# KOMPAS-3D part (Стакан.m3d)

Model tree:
1. Эскиз:1
2. Операция выдавливания:1
     Расстояние 1 = 70; Угол 1 = 4
3. Эскиз:2
4. Вырезать элемент выдавливания:1
     Расстояние 1 = 65; Угол 1 = 4
5. Эскиз:3
6. Вырезать элемент выдавливания:2
     Толщина стенки 2 = 2; Расстояние 1 = 75; Угол 1 = 4
7. Скругление:1
     Радиус = 5
8. Эскиз:4
9. Операция выдавливания:3
     Расстояние 1 = 10; Расстояние 2 = 70; Угол 2 = 1
10. Скругление:2
     Радиус = 1
11. Скругление:3
     Радиус = 1
12. Смещенная плоскость:1
     Расстояние = 65
13. Эскиз:5
14. Скругление:6
     Радиус = 3

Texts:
  Made in Ukraine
